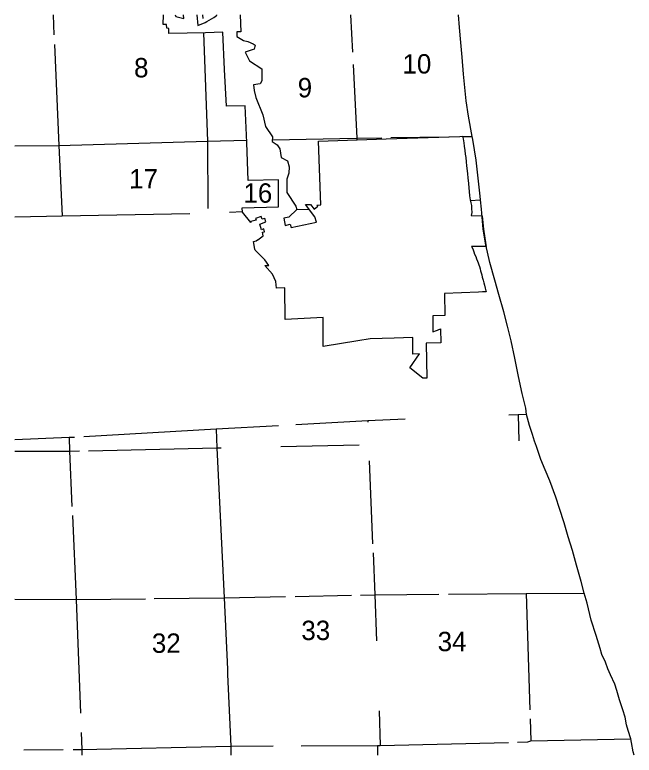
# Model space of a CAD drawing. Extents: x -2096698 to 6160, y -2144490 to 6200.
# Drawn here: x -2096698 to -2074784, y -2144490 to -2118284 of the extents above; entities that cross this region are included whole.
import ezdxf

# ---------------------------------------------------------------- set-up
doc = ezdxf.new("R2010")
doc.units = 0
for name, color, linetype in [('tdCoCorpBndry', 7, 'Continuous'), ('tdCoSectLinePart', 7, 'Continuous'), ('tdCoSectNmbr', 7, 'Continuous')]:
    doc.layers.add(name, color=color, linetype=linetype)

msp = doc.modelspace()

# ---------------------------------------------------------------- linework, layer by layer
at = {"layer": 'tdCoCorpBndry'}
for points in [[(-2088724, -2118284), (-2088705, -2118887), (-2088844, -2118891), (-2088842, -2119050), (-2088604, -2119197), (-2088450, -2119224), (-2088268, -2119308), (-2088200, -2119360), (-2088232, -2119497), (-2088546, -2119610), (-2088395, -2119912), (-2087962, -2120191), (-2087954, -2120618), (-2088013, -2120731), (-2088259, -2120757), (-2088230, -2120966), (-2088174, -2121214), (-2087918, -2121827), (-2087828, -2122237), (-2087578, -2122601), (-2087589, -2122774), (-2087416, -2122890), (-2087317, -2123029), (-2087273, -2123331), (-2087050, -2123455), (-2086994, -2123670), (-2086998, -2123894), (-2087071, -2124104), (-2087070, -2124578), (-2086761, -2125054), (-2086720, -2125175), (-2087002, -2125445), (-2087183, -2125483), (-2087130, -2125736), (-2086952, -2125696), (-2086923, -2125816), (-2086030, -2125619), (-2086080, -2125429), (-2086412, -2125000), (-2086240, -2124998), (-2086104, -2125164), (-2085979, -2125060), (-2086009, -2125016), (-2085873, -2125011), (-2085959, -2122752), (-2083559, -2122673), (-2080958, -2122587), (-2080853, -2122584), (-2080831, -2122679), (-2080815, -2122818), (-2080800, -2122938), (-2080778, -2123083), (-2080762, -2123218), (-2080745, -2123336), (-2080727, -2123489), (-2080714, -2123635), (-2080697, -2123802), (-2080685, -2123908), (-2080665, -2124051), (-2080650, -2124254), (-2080632, -2124406), (-2080618, -2124541), (-2080610, -2124693), (-2080592, -2124828), (-2080561, -2124939), (-2080545, -2125034), (-2080538, -2125154), (-2080528, -2125264), (-2080529, -2125285), (-2080556, -2125388), (-2080163, -2125396), (-2080120, -2125877), (-2080034, -2126421), (-2080021, -2126480), (-2080027, -2126480), (-2080539, -2126485), (-2080511, -2126516), (-2080485, -2126601), (-2080460, -2126672), (-2080431, -2126753), (-2080387, -2126837), (-2080362, -2126920), (-2080331, -2126999), (-2080308, -2127062), (-2080281, -2127129), (-2080258, -2127196), (-2080237, -2127273), (-2080218, -2127344), (-2080193, -2127417), (-2080174, -2127491), (-2080158, -2127572), (-2080130, -2127671), (-2080102, -2127768), (-2080081, -2127851), (-2080058, -2127962), (-2080032, -2128059), (-2080025, -2128085), (-2080156, -2128090), (-2080287, -2128096), (-2081495, -2128147), (-2081484, -2128923), (-2081911, -2128941), (-2081907, -2129477), (-2081906, -2129503), (-2081782, -2129457), (-2081739, -2129441), (-2081716, -2129433), (-2081638, -2129404), (-2081621, -2129891), (-2082143, -2129909), (-2082119, -2131143), (-2082257, -2131151), (-2082724, -2130776), (-2082374, -2130282), (-2082620, -2130298), (-2082619, -2130082), (-2082620, -2129704), (-2083271, -2129727), (-2084131, -2129757), (-2084557, -2129827), (-2085788, -2130029), (-2085794, -2129001), (-2087135, -2129063), (-2087141, -2127942), (-2087445, -2127957), (-2087459, -2127728), (-2087582, -2127463), (-2087852, -2127162), (-2087708, -2127162), (-2087858, -2126961), (-2088120, -2126691), (-2088196, -2126612), (-2088203, -2126578), (-2088257, -2126309), (-2088163, -2126286), (-2088112, -2126249), (-2088102, -2126243), (-2087910, -2126106), (-2087939, -2125982), (-2087859, -2125960), (-2087886, -2125862), (-2087966, -2125889), (-2088028, -2125698), (-2087813, -2125617), (-2087855, -2125488), (-2087949, -2125519), (-2087980, -2125428), (-2088180, -2125491), (-2088160, -2125551), (-2088353, -2125605), (-2088348, -2125636), (-2088642, -2125271), (-2088659, -2125118), (-2087371, -2125081), (-2087373, -2124121), (-2088446, -2124147), (-2088489, -2122804), (-2088551, -2121503), (-2089212, -2121520), (-2089274, -2120219), (-2089337, -2118904), (-2089952, -2118919), (-2091247, -2118946), (-2091251, -2118770), (-2091324, -2118762), (-2091333, -2118625), (-2091448, -2118628), (-2091432, -2118284)], [(-2091026, -2118284), (-2091007, -2118341), (-2090715, -2118411), (-2090732, -2118284)], [(-2090256, -2118284), (-2090223, -2118664), (-2090164, -2118643), (-2089964, -2118552), (-2089905, -2118523), (-2089739, -2118432), (-2089657, -2118383), (-2089559, -2118308), (-2089545, -2118298), (-2089546, -2118284)]]:
    msp.add_lwpolyline(points, dxfattribs=at)
at = {"layer": 'tdCoSectLinePart'}
for p, q in [((-2095345, -2118284), (-2095314, -2118990)), ((-2090053, -2118284), (-2090048, -2118416)), ((-2084825, -2118284), (-2084755, -2119606)), ((-2096698, -2122916), (-2095139, -2122909)), ((-2096698, -2125433), (-2095024, -2125403)), ((-2094773, -2133251), (-2096698, -2133327)), ((-2096698, -2133734), (-2094762, -2133728)), ((-2096698, -2138970), (-2094533, -2138982)), ((-2089061, -2144167), (-2089056, -2144490)), ((-2083866, -2144148), (-2083861, -2144490)), ((-2094326, -2144284), (-2094322, -2144490))]:
    msp.add_line(p, q, dxfattribs=at)
for points in [[(-2080519, -2122587), (-2080651, -2121866), (-2080732, -2121334), (-2080828, -2120390), (-2080869, -2119780), (-2080916, -2119260), (-2080969, -2118734), (-2081002, -2118284)], [(-2090028, -2118920), (-2089875, -2122752)], [(-2095298, -2119336), (-2095139, -2122909)], [(-2084731, -2120046), (-2084593, -2122649)], [(-2087586, -2122708), (-2084593, -2122649)], [(-2084593, -2122649), (-2083717, -2122636)], [(-2084593, -2122649), (-2084592, -2122707)], [(-2083398, -2122631), (-2081355, -2122600)], [(-2080853, -2122592), (-2080519, -2122587)], [(-2080221, -2124837), (-2080236, -2124702), (-2080307, -2124061), (-2080378, -2123430), (-2080489, -2122692), (-2080519, -2122587)], [(-2095139, -2122909), (-2089875, -2122752)], [(-2095139, -2122909), (-2095024, -2125403)], [(-2089875, -2122752), (-2088494, -2122725)], [(-2089875, -2122752), (-2089871, -2125140)], [(-2080585, -2124859), (-2080221, -2124837)], [(-2078596, -2132435), (-2078619, -2132203), (-2078751, -2131689), (-2078875, -2131088), (-2079003, -2130438), (-2079138, -2129825), (-2079266, -2129300), (-2079393, -2128796), (-2079570, -2128183), (-2079717, -2127671), (-2079896, -2127049), (-2080036, -2126421), (-2080122, -2125877), (-2080184, -2125168), (-2080221, -2124837)], [(-2095024, -2125403), (-2090506, -2125311)], [(-2089100, -2125269), (-2088646, -2125251)], [(-2086725, -2125178), (-2086289, -2125162)], [(-2086113, -2125155), (-2086094, -2125154)], [(-2084210, -2132656), (-2086751, -2132795)], [(-2082892, -2132602), (-2084210, -2132656)], [(-2084210, -2132656), (-2084209, -2132698)], [(-2078883, -2132440), (-2079215, -2132453)], [(-2078596, -2132435), (-2078883, -2132440)], [(-2078883, -2132440), (-2078865, -2133364)], [(-2078312, -2133370), (-2078384, -2133144), (-2078484, -2132817), (-2078596, -2132435)], [(-2087365, -2132829), (-2089572, -2132951)], [(-2089572, -2132951), (-2094256, -2133221)], [(-2089572, -2132951), (-2089554, -2133614)], [(-2094583, -2133240), (-2094773, -2133251)], [(-2094773, -2133251), (-2094762, -2133728)], [(-2076556, -2138755), (-2076655, -2138342), (-2076830, -2137761), (-2076972, -2137244), (-2077118, -2136756), (-2077264, -2136264), (-2077427, -2135756), (-2077553, -2135354), (-2077772, -2134780), (-2077930, -2134386), (-2078085, -2134028), (-2078237, -2133565), (-2078312, -2133370)], [(-2094093, -2133713), (-2089554, -2133614)], [(-2089554, -2133614), (-2089397, -2133611)], [(-2089554, -2133614), (-2089287, -2138916)], [(-2087289, -2133563), (-2084516, -2133501)], [(-2094762, -2133728), (-2094415, -2133720)], [(-2094762, -2133728), (-2094677, -2135687)], [(-2084163, -2134073), (-2084038, -2137010)], [(-2094663, -2136010), (-2094533, -2138982)], [(-2084024, -2137326), (-2083961, -2138815)], [(-2094533, -2138982), (-2092079, -2138951)], [(-2091763, -2138947), (-2089287, -2138916)], [(-2089287, -2138916), (-2087126, -2138875)], [(-2089287, -2138916), (-2089171, -2141451), (-2089177, -2141639), (-2089061, -2144167)], [(-2086783, -2138869), (-2084788, -2138831)], [(-2084471, -2138825), (-2083961, -2138815)], [(-2083961, -2138815), (-2081695, -2138793)], [(-2083961, -2138815), (-2083902, -2140441)], [(-2081359, -2138790), (-2078601, -2138763)], [(-2078601, -2138763), (-2076556, -2138755)], [(-2078601, -2138763), (-2078472, -2142883)], [(-2074906, -2143912), (-2074995, -2143613), (-2075055, -2143411), (-2075105, -2143146), (-2075188, -2142879), (-2075298, -2142528), (-2075400, -2142201), (-2075469, -2141978), (-2075618, -2141649), (-2075712, -2141434), (-2075804, -2141195), (-2075930, -2140927), (-2075986, -2140709), (-2076134, -2140252), (-2076304, -2139707), (-2076449, -2139108), (-2076556, -2138755)], [(-2094533, -2138982), (-2094376, -2143004)], [(-2083811, -2142923), (-2083767, -2144148)], [(-2078462, -2143201), (-2078437, -2143982)], [(-2094349, -2143691), (-2094326, -2144284)], [(-2078437, -2143982), (-2074906, -2143912)], [(-2074784, -2144490), (-2074817, -2144372), (-2074881, -2144044), (-2074906, -2143912)], [(-2094326, -2144284), (-2089061, -2144167)], [(-2089061, -2144167), (-2087559, -2144161)], [(-2086563, -2144158), (-2083866, -2144148)], [(-2083866, -2144148), (-2083767, -2144148)], [(-2083767, -2144148), (-2079231, -2144035)], [(-2078909, -2144027), (-2078541, -2144018)], [(-2078541, -2144018), (-2078437, -2143982)], [(-2096382, -2144296), (-2094982, -2144288)], [(-2094634, -2144285), (-2094326, -2144284)]]:
    msp.add_lwpolyline(points, dxfattribs=at)

# ---------------------------------------------------------------- texts
at = {"layer": 'tdCoSectNmbr'}
for s, height, rotation, p in [('8', 686, 0.0882, (-2092479, -2120499)), ('10', 686.4, 0.0896, (-2082982, -2120364)), ('9', 686, 0.089, (-2086688, -2121206)), ('17', 686.4, 0.0881, (-2092653, -2124432)), ('16', 686.4, 0.0889, (-2088609, -2124936)), ('33', 686.4, 0.089, (-2086560, -2140416)), ('32', 686.4, 0.0881, (-2091848, -2140868)), ('34', 686.4, 0.0898, (-2081737, -2140810))]:
    msp.add_text(s, height=height, rotation=rotation, dxfattribs=at).set_placement(p)

doc.saveas('drawing.dxf')
